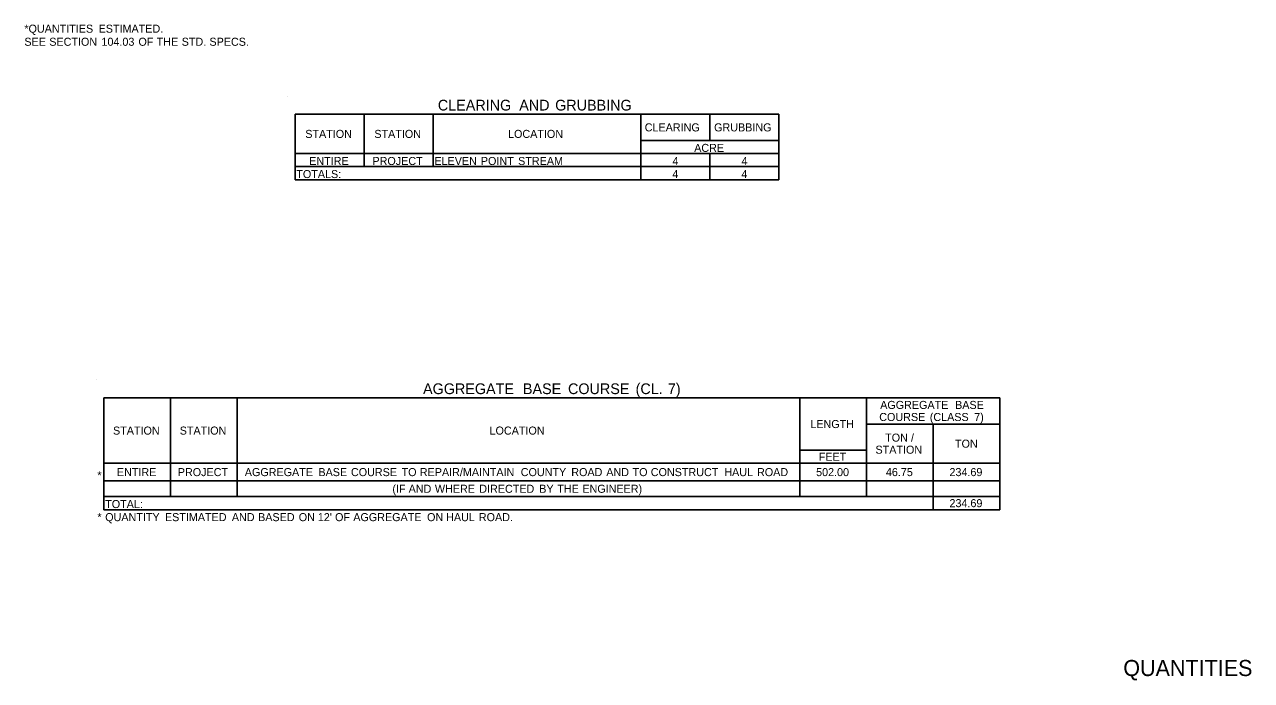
# Model space of a CAD drawing. Extents: x -2001791 to 62654501, y -2521700 to -592476.
# Drawn here: x -2001252 to -2000338, y -593470 to -592981 of the extents above; entities that cross this region are included whole.
import ezdxf

# ---------------------------------------------------------------- set-up
doc = ezdxf.new("R2010")
doc.units = 0
for name, color, linetype in [('Default', 7, 'Continuous'), ('R_Border', 7, 'Continuous'), ('R_Border Prem', 7, 'Continuous')]:
    doc.layers.add(name, color=color, linetype=linetype)

msp = doc.modelspace()

# ---------------------------------------------------------------- linework, layer by layer
at = {"layer": 'Default'}
for p, q in [((-2001050.68, -593047.98), (-2000689.93, -593047.98)), ((-2001050.68, -593096.73), (-2001050.68, -593047.98)), ((-2001050.68, -593096.73), (-2001050.68, -593047.98)), ((-2000999.2, -593086.98), (-2000999.2, -593047.98)), ((-2000947.72, -593086.98), (-2000947.72, -593047.98)), ((-2000792.89, -593096.73), (-2000792.89, -593047.98)), ((-2000741.41, -593067.48), (-2000741.41, -593047.98)), ((-2000689.93, -593096.73), (-2000689.93, -593047.98)), ((-2000689.93, -593067.48), (-2000689.93, -593047.98)), ((-2000792.89, -593067.48), (-2000689.93, -593067.48)), ((-2000792.89, -593086.98), (-2000792.89, -593067.48)), ((-2001050.68, -593077.23), (-2000689.93, -593077.23)), ((-2000999.2, -593086.98), (-2000999.2, -593077.23)), ((-2000947.72, -593086.98), (-2000947.72, -593077.23)), ((-2000741.41, -593096.73), (-2000741.41, -593077.23)), ((-2000741.41, -593096.73), (-2000741.41, -593077.23)), ((-2000689.93, -593086.98), (-2000689.93, -593077.23)), ((-2001050.68, -593086.98), (-2000689.93, -593086.98)), ((-2000947.72, -593086.98), (-2000689.93, -593086.98)), ((-2001050.68, -593096.73), (-2000689.93, -593096.73)), ((-2001193.16, -593259.44), (-2000525.29, -593259.44)), ((-2001193.16, -593342.8), (-2001193.16, -593259.44)), ((-2001193.16, -593342.8), (-2001193.16, -593259.44)), ((-2001143.44, -593333.05), (-2001143.44, -593259.44)), ((-2001093.71, -593333.05), (-2001093.71, -593259.44)), ((-2000674.46, -593333.05), (-2000674.46, -593259.44)), ((-2000624.74, -593333.05), (-2000624.74, -593259.44)), ((-2000525.29, -593342.8), (-2000525.29, -593259.44)), ((-2000624.74, -593278.94), (-2000525.29, -593278.94)), ((-2000575.01, -593342.8), (-2000575.01, -593278.94)), ((-2000525.29, -593342.8), (-2000525.29, -593278.94)), ((-2000674.46, -593298.44), (-2000624.74, -593298.44)), ((-2000624.74, -593333.05), (-2000624.74, -593298.44)), ((-2001193.16, -593308.19), (-2000525.29, -593308.19)), ((-2001143.44, -593333.05), (-2001143.44, -593308.19)), ((-2001093.71, -593333.05), (-2001093.71, -593308.19)), ((-2000674.46, -593333.05), (-2000674.46, -593308.19)), ((-2000624.74, -593308.19), (-2000525.29, -593308.19)), ((-2000575.01, -593342.8), (-2000575.01, -593308.19)), ((-2001193.16, -593321.35), (-2000525.29, -593321.35)), ((-2001193.16, -593333.05), (-2000525.29, -593333.05)), ((-2001193.16, -593342.8), (-2000525.29, -593342.8))]:
    msp.add_line(p, q, dxfattribs=at)
at = {"layer": 'R_Border'}
for p, q in [((-2001056.53, -593034.33), (-2001056.53, -593034.33)), ((-2001199.01, -593245.79), (-2001199.01, -593245.79))]:
    msp.add_line(p, q, dxfattribs=at)

# ---------------------------------------------------------------- texts
at = {"layer": 'Default'}
for s, height, p in [('*QUANTITIES', 6, (-2001252.44, -592987.13)), (' ESTIMATED.', 6, (-2001199.31, -592987.13)), ('SEE', 6, (-2001252.44, -592996.88)), (' SECTION', 6, (-2001236.11, -592996.88)), (' 104.03', 6, (-2001197.2, -592996.88)), (' OF', 6, (-2001169.63, -592996.88)), (' THE', 6, (-2001156.04, -592996.88)), (' STD.', 6, (-2001137.39, -592996.88)), (' SPECS.', 6, (-2001116.7, -592996.88)), ('CLEARING', 8, (-2000944.19, -593045.15)), (' AND', 8, (-2000886.49, -593045.15)), (' GRUBBING', 8, (-2000859.72, -593045.15)), ('STATION', 6, (-2001043.01, -593065.6)), ('STATION', 6, (-2000991.53, -593065.6)), ('LOCATION', 6, (-2000891.86, -593065.6)), ('CLEARING', 6, (-2000789.96, -593060.73)), ('GRUBBING', 6, (-2000738.24, -593060.73)), ('ACRE', 6, (-2000753.09, -593076.03)), ('ENTIRE', 6, (-2001040.09, -593085.78)), ('PROJECT', 6, (-2000992.95, -593085.78)), ('ELEVEN', 6, (-2000946.75, -593085.78)), (' POINT', 6, (-2000914.35, -593085.78)), (' STREAM', 6, (-2000886.57, -593085.78)), ('4', 6, (-2000769.28, -593085.78)), ('4', 6, (-2000717.8, -593085.78)), ('TOTALS:', 6, (-2001049.71, -593095.53)), ('4', 6, (-2000769.39, -593095.53)), ('4', 6, (-2000717.91, -593095.53)), ('AGGREGATE', 8, (-2000955.22, -593256.62)), (' BASE', 8, (-2000883.73, -593256.62)), (' COURSE', 8, (-2000850.12, -593256.62)), (' (CL.', 8, (-2000799.74, -593256.62)), (' 7)', 8, (-2000775.68, -593256.62)), ('AGGREGATE', 6, (-2000614.42, -593267.69)), (' BASE', 6, (-2000560.8, -593267.69)), ('LENGTH', 6, (-2000666.51, -593281.94)), ('COURSE', 6, (-2000615.14, -593276.69)), (' (CLASS', 6, (-2000579.68, -593276.69)), (' 7)', 6, (-2000546.56, -593276.69)), ('STATION', 6, (-2001186.36, -593286.82)), ('STATION', 6, (-2001136.64, -593286.82)), ('LOCATION', 6, (-2000905.64, -593286.82)), ('TON', 6, (-2000610.72, -593292.07)), (' /', 6, (-2000593.69, -593292.07)), ('STATION', 6, (-2000617.94, -593301.07)), ('TON', 6, (-2000558.66, -593296.57)), ('FEET', 6, (-2000660.23, -593306.32)), ('*', 6, (-2001198.04, -593320.15)), ('ENTIRE', 6, (-2001183.45, -593317.77)), ('PROJECT', 6, (-2001138.06, -593317.77)), ('AGGREGATE', 6, (-2001088.12, -593317.77)), (' BASE', 6, (-2001035.46, -593317.77)), (' COURSE', 6, (-2001011.2, -593317.77)), (' TO', 6, (-2000973.45, -593317.77)), (' REPAIR/MAINTAIN', 6, (-2000959.86, -593317.77)), (' COUNTY', 6, (-2000884.61, -593317.77)), (' ROAD', 6, (-2000846.95, -593317.77)), (' AND', 6, (-2000820.85, -593317.77)), (' TO', 6, (-2000801.26, -593317.77)), (' CONSTRUCT', 6, (-2000787.67, -593317.77)), (' HAUL', 6, (-2000732.88, -593317.77)), (' ROAD', 6, (-2000708.48, -593317.77)), ('502.00', 6, (-2000662.21, -593317.77)), ('46.75', 6, (-2000610.19, -593317.77)), ('234.69', 6, (-2000562.78, -593317.77)), ('(IF', 6, (-2000978.07, -593330.2)), (' AND', 6, (-2000968.21, -593330.2)), (' WHERE', 6, (-2000948.63, -593330.2)), (' DIRECTED', 6, (-2000915.54, -593330.2)), (' BY', 6, (-2000870.81, -593330.2)), (' THE', 6, (-2000857.36, -593330.2)), (' ENGINEER)', 6, (-2000838.71, -593330.2)), ('TOTAL:', 6, (-2001192.19, -593341.6)), ('234.69', 6, (-2000562.77, -593340.93)), ('*', 6, (-2001198.04, -593351.35)), ('QUANTITY', 6, (-2001192.19, -593351.35)), (' ESTIMATED', 6, (-2001149.86, -593351.35)), (' AND', 6, (-2001100, -593351.35)), (' BASED', 6, (-2001080.42, -593351.35)), (' ON', 6, (-2001050.11, -593351.35)), (" 12'", 6, (-2001035.89, -593351.35)), (' OF', 6, (-2001023.04, -593351.35)), (' AGGREGATE', 6, (-2001009.45, -593351.35)), (' ON', 6, (-2000954.46, -593351.35)), (' HAUL', 6, (-2000940.24, -593351.35)), (' ROAD.', 6, (-2000915.85, -593351.35))]:
    msp.add_text(s, height=height, dxfattribs=at).set_placement(p)
at = {"layer": 'R_Border Prem'}
msp.add_text('QUANTITIES', height=12, dxfattribs=at).set_placement((-2000433.2, -593466.85))

doc.saveas('drawing.dxf')
